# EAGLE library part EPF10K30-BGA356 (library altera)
EPF10K30 FLEX 10K family
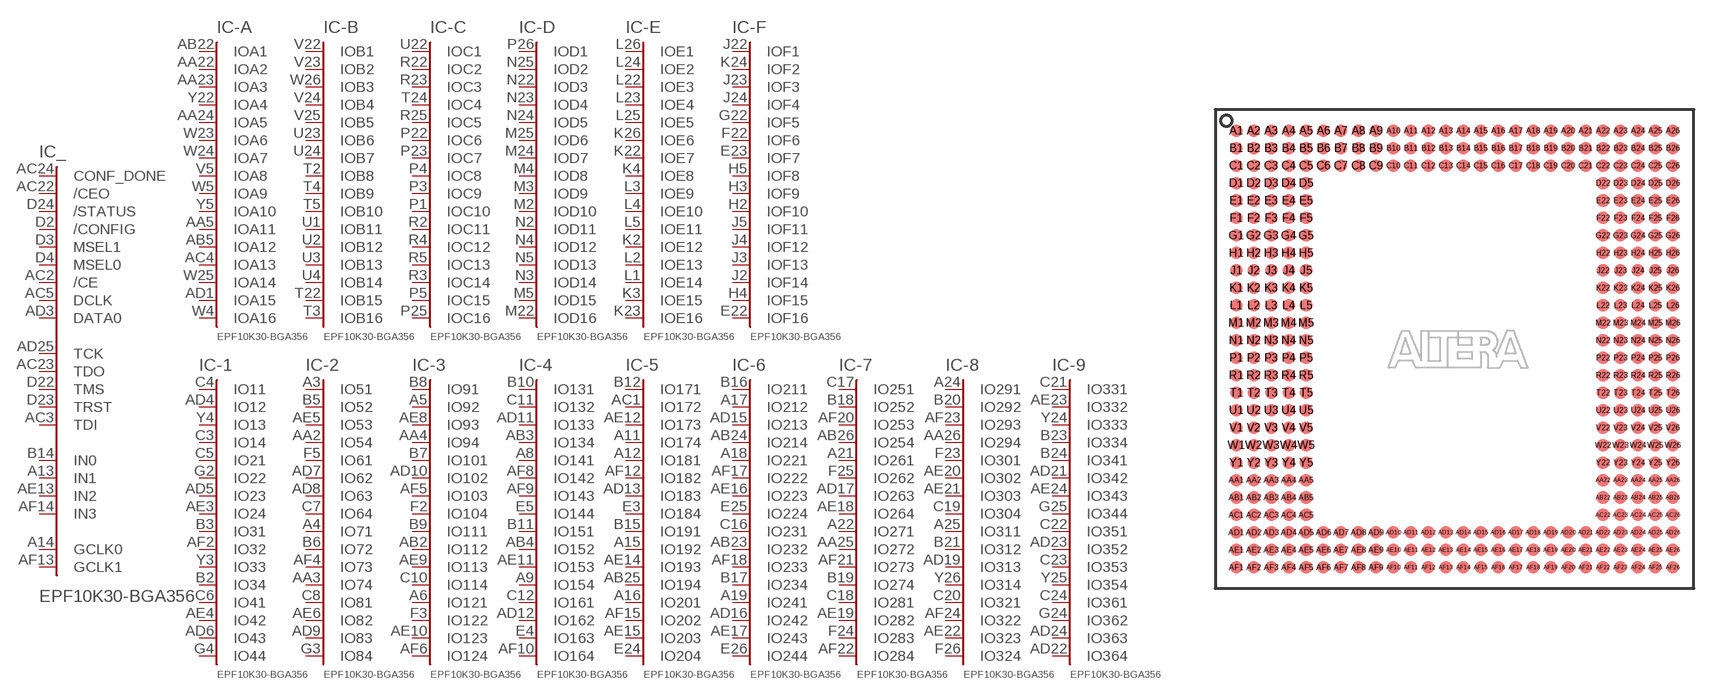
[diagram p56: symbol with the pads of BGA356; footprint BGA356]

Designator prefix IC; gates _=100R240C -A=A16 -B=B16 -C=C16 -D=D16 -E=E16 -1=IO44 -2=IO84 -3=IO124 -4=IO164 -5=IO204 -6=IO244 -7=IO284 -8=IO324 -9=IO364 -F=F16 G1=GNDINT G2=GNDINT G3=GNDINT G4=GNDINT G5=GNDINT G6=GNDINT G7=GNDINT G8=GNDINT G9=GNDINT G10=GNDINT G11=GNDINT G12=GNDINT G13=GNDINT G14=GNDINT G15=GNDINT G16=GNDINT G17=GNDINT G18=GNDINT G19=GNDINT G20=GNDINT G21=GNDINT G22=GNDINT G23=GNDINT G24=GNDINT G25=GNDINT G26=GNDINT G27=GNDINT G28=GNDINT G29=GNDINT G30=GNDINT G31=GNDINT G32=GNDINT G33=GNDINT NC1=NC NC2=NC NC3=NC NC4=NC NC5=NC NC6=NC NC7=NC NC8=NC NC9=NC NC10=NC NC11=NC NC12=NC NC13=NC NC14=NC NC15=NC NC16=NC NC17=NC NC18=NC NC19=NC NC20=NC NC21=NC NC22=NC NC23=NC NC24=NC NC25=NC NC26=NC NC27=NC NC28=NC V1=VCCINT V2=VCCINT V3=VCCINT V4=VCCINT V5=VCCINT V6=VCCINT V7=VCCINT V8=VCCINT V9=VCCINT V10=VCCINT V11=VCCINT V12=VCCINT V13=VCCINT V14=VCCINT V15=VCCINT V16=VCCINT VO1=VCCIO VO2=VCCIO VO3=VCCIO VO4=VCCIO VO5=VCCIO VO6=VCCIO VO7=VCCIO VO8=VCCIO VO9=VCCIO VO10=VCCIO VO11=VCCIO VO12=VCCIO VO13=VCCIO VO14=VCCIO VO15=VCCIO VO16=VCCIO VO17=VCCIO VO18=VCCIO VO19=VCCIO

## EPF10K30-BGA356 (MPN: EPF10K30ABC356-2; OC_FARNELL: unknown; OC_NEWARK: 51R8936)  [BGA356]
A1  V5:VCC  pwr
A2  G17:GND  pwr
A3  -2:IO51
A4  -2:IO71
A5  -3:IO92
A6  -3:IO121
A7  VO7:VCCIO  pwr
A8  -4:IO141
A9  -4:IO154
A10  G16:GND  pwr
A11  -5:IO174
A12  -5:IO181
A13  _:IN1  in
A14  _:GCLK0  in
A15  -5:IO192
A16  -5:IO201
A17  -6:IO212
A18  -6:IO221
A19  -6:IO241
A20  G15:GND  pwr
A21  -7:IO261
A22  -7:IO271
A23  VO8:VCCIO  pwr
A24  -8:IO291
A25  -8:IO311
A26  V6:VCC  pwr
AA1  V1:VCC  pwr
AA2  -2:IO54
AA3  -2:IO74
AA4  -3:IO94
AA5  -A:IOA11
AA22  -A:IOA2
AA23  -A:IOA3
AA24  -A:IOA5
AA25  -7:IO272
AA26  -8:IO294
AB1  VO1:VCCIO  pwr
AB2  -3:IO112
AB3  -4:IO134
AB4  -4:IO152
AB5  -A:IOA12
AB22  -A:IOA1
AB23  -6:IO232
AB24  -6:IO214
AB25  -5:IO194
AB26  -7:IO254
AC1  -5:IO172
AC2  _:/CE  in
AC3  _:TDI
AC4  -A:IOA13
AC5  _:DCLK  in
AC22  _:/CEO  in
AC23  _:TDO
AC24  _:CONF_DONE  in
AC25  VO2:VCCIO  pwr
AC26  NC1:NC  nc
AD1  -A:IOA15
AD2  G1:GND  pwr
AD3  _:DATA0  in
AD4  -1:IO12
AD5  -1:IO23
AD6  -1:IO43
AD7  -2:IO62
AD8  -2:IO63
AD9  -2:IO83
AD10  -3:IO102
AD11  -4:IO133
AD12  -4:IO162
AD13  -5:IO183
AD14  G2:GND  pwr
AD15  -6:IO213
AD16  -6:IO242
AD17  -7:IO263
AD18  VO3:VCCIO  pwr
AD19  -8:IO313
AD20  G3:GND  pwr
AD21  -9:IO342
AD22  -9:IO364
AD23  -9:IO352
AD24  -9:IO363
AD25  _:TCK
AD26  V2:VCC  pwr
AE1  G4:GND  pwr
AE2  G5:GND  pwr
AE3  -1:IO24
AE4  -1:IO42
AE5  -2:IO53
AE6  -2:IO82
AE7  G6:GND  pwr
AE8  -3:IO93
AE9  -3:IO113
AE10  -3:IO123
AE11  -4:IO153
AE12  -5:IO173
AE13  _:IN2  in
AE14  -5:IO193
AE15  -5:IO203
AE16  -6:IO223
AE17  -6:IO243
AE18  -7:IO264
AE19  -7:IO282
AE20  -8:IO302
AE21  -8:IO303
AE22  -8:IO323
AE23  -9:IO332
AE24  -9:IO343
AE25  G7:GND  pwr
AE26  G8:GND  pwr
AF1  V3:VCC  pwr
AF2  -1:IO32
AF3  VO4:VCCIO  pwr
AF4  -2:IO73
AF5  -3:IO103
AF6  -3:IO124
AF7  VO5:VCCIO  pwr
AF8  -4:IO142
AF9  -4:IO143
AF10  -4:IO164
AF11  G9:GND  pwr
AF12  -5:IO182
AF13  _:GCLK1  in
AF14  _:IN3  in
AF15  -5:IO202
AF16  VO6:VCCIO  pwr
AF17  -6:IO222
AF18  -6:IO233
AF19  G10:GND  pwr
AF20  -7:IO253
AF21  -7:IO273
AF22  -7:IO284
AF23  -8:IO293
AF24  -8:IO322
AF25  G18:GND  pwr
AF26  V4:VCC  pwr
B1  G14:GND  pwr
B2  -1:IO34
B3  -1:IO31
B4  VO9:VCCIO  pwr
B5  -2:IO52
B6  -2:IO72
B7  -3:IO101
B8  -3:IO91
B9  -3:IO111
B10  -4:IO131
B11  -4:IO151
B12  -5:IO171
B13  G13:GND  pwr
B14  _:IN0  in
B15  -5:IO191
B16  -6:IO211
B17  -6:IO234
B18  -7:IO252
B19  -7:IO274
B20  -8:IO292
B21  -8:IO312
B22  G12:GND  pwr
B23  -9:IO334
B24  -9:IO341
B25  G11:GND  pwr
B26  G19:GND  pwr
C1  NC2:NC  nc
C2  G20:GND  pwr
C3  -1:IO14
C4  -1:IO11
C5  -1:IO21
C6  -1:IO41
C7  -2:IO64
C8  -2:IO81
C9  G21:GND  pwr
C10  -3:IO114
C11  -4:IO132
C12  -4:IO161
C13  G22:GND  pwr
C14  V7:VCC  pwr
C15  VO10:VCCIO  pwr
C16  -6:IO231
C17  -7:IO251
C18  -7:IO281
C19  -8:IO304
C20  -8:IO321
C21  -9:IO331
C22  -9:IO351
C23  -9:IO353
C24  -9:IO361
C25  G23:GND  pwr
C26  V8:VCC  pwr
D1  NC3:NC  nc
D2  _:/CONFIG  in
D3  _:MSEL1  in
D4  _:MSEL0  in
D5  V9:VCC  pwr
D22  _:TMS
D23  _:TRST
D24  _:/STATUS  in
D25  VO11:VCCIO  pwr
D26  NC4:NC  nc
E1  NC5:NC  nc
E2  NC6:NC  nc
E3  -5:IO184
E4  -4:IO163
E5  -4:IO144
E22  -F:IOF16
E23  -F:IOF7
E24  -5:IO204
E25  -6:IO224
E26  -6:IO244
F1  V10:VCC  pwr
F2  -3:IO104
F3  -3:IO122
F4  VO12:VCCIO  pwr
F5  -2:IO61
F22  -F:IOF6
F23  -8:IO301
F24  -7:IO283
F25  -7:IO262
F26  -8:IO324
G1  NC7:NC  nc
G2  -1:IO22
G3  -2:IO84
G4  -1:IO44
G5  NC8:NC  nc
G22  -F:IOF5
G23  NC9:NC  nc
G24  -9:IO362
G25  -9:IO344
G26  NC10:NC  nc
H1  NC11:NC  nc
H2  -F:IOF10
H3  -F:IOF9
H4  -F:IOF15
H5  -F:IOF8
H22  V11:VCC  pwr
H23  G24:GND  pwr
H24  VO13:VCCIO  pwr
H25  NC12:NC  nc
H26  NC13:NC  nc
J1  V12:VCC  pwr
J2  -F:IOF14
J3  -F:IOF13
J4  -F:IOF12
J5  -F:IOF11
J22  -F:IOF1
J23  -F:IOF3
J24  -F:IOF4
J25  NC14:NC  nc
J26  G25:GND  pwr
K1  G26:GND  pwr
K2  -E:IOE12
K3  -E:IOE15
K4  -E:IOE8
K5  VO14:VCCIO  pwr
K22  -E:IOE7
K23  -E:IOE16
K24  -F:IOF2
K25  NC15:NC  nc
K26  -E:IOE6
L1  -E:IOE14
L2  -E:IOE13
L3  -E:IOE9
L4  -E:IOE10
L5  -E:IOE11
L22  -E:IOE3
L23  -E:IOE4
L24  -E:IOE2
L25  -E:IOE5
L26  -E:IOE1
M1  G27:GND  pwr
M2  -D:IOD10
M3  -D:IOD9
M4  -D:IOD8
M5  -D:IOD15
M22  -D:IOD16
M23  VO15:VCCIO  pwr
M24  -D:IOD7
M25  -D:IOD6
M26  V13:VCC  pwr
N1  V14:VCC  pwr
N2  -D:IOD11
N3  -D:IOD14
N4  -D:IOD12
N5  -D:IOD13
N22  -D:IOD3
N23  -D:IOD4
N24  -D:IOD5
N25  -D:IOD2
N26  G28:GND  pwr
P1  -C:IOC10
P2  VO16:VCCIO  pwr
P3  -C:IOC9
P4  -C:IOC8
P5  -C:IOC15
P22  -C:IOC6
P23  -C:IOC7
P24  NC16:NC  nc
P25  -C:IOC16
P26  -D:IOD1
R1  G29:GND  pwr
R2  -C:IOC11
R3  -C:IOC14
R4  -C:IOC12
R5  -C:IOC13
R22  -C:IOC2
R23  -C:IOC3
R24  NC17:NC  nc
R25  -C:IOC5
R26  G30:GND  pwr
T1  G31:GND  pwr
T2  -B:IOB8
T3  -B:IOB16
T4  -B:IOB9
T5  -B:IOB10
T22  -B:IOB15
T23  NC18:NC  nc
T24  -C:IOC4
T25  VO17:VCCIO  pwr
T26  V15:VCC  pwr
U1  -B:IOB11
U2  -B:IOB12
U3  -B:IOB13
U4  -B:IOB14
U5  V16:VCC  pwr
U22  -C:IOC1
U23  -B:IOB6
U24  -B:IOB7
U25  NC19:NC  nc
U26  G32:GND  pwr
V1  NC20:NC  nc
V2  VO18:VCCIO  pwr
V3  NC21:NC  nc
V4  NC22:NC  nc
V5  -A:IOA8
V22  -B:IOB1
V23  -B:IOB2
V24  -B:IOB4
V25  -B:IOB5
V26  NC23:NC  nc
W1  G33:GND  pwr
W2  NC24:NC  nc
W3  NC25:NC  nc
W4  -A:IOA16
W5  -A:IOA9
W22  VO19:VCCIO  pwr
W23  -A:IOA6
W24  -A:IOA7
W25  -A:IOA14
W26  -B:IOB3
Y1  NC26:NC  nc
Y2  NC27:NC  nc
Y3  -1:IO33
Y4  -1:IO13
Y5  -A:IOA10
Y22  -A:IOA4
Y23  NC28:NC  nc
Y24  -9:IO333
Y25  -9:IO354
Y26  -8:IO314

## Footprint BGA356 (pad centres in mm)
Ball Grid Array
smd 0.9 x 0.9: A1 -15.875,15.875; A2 -14.605,15.875; A3 -13.335,15.875; A4 -12.065,15.875; A5 -10.795,15.875; A6 -9.525,15.875; A7 -8.255,15.875; A8 -6.985,15.875; A9 -5.715,15.875; A10 -4.445,15.875; A11 -3.175,15.875; A12 -1.905,15.875; A13 -0.635,15.875; A14 0.635,15.875; A15 1.905,15.875; A16 3.175,15.875; A17 4.445,15.875; A18 5.715,15.875; A19 6.985,15.875; A20 8.255,15.875; A21 9.525,15.875; A22 10.795,15.875; A23 12.065,15.875; A24 13.335,15.875; A25 14.605,15.875; A26 15.875,15.875; AA1 -15.875,-9.525; AA2 -14.605,-9.525; AA3 -13.335,-9.525; AA4 -12.065,-9.525; AA5 -10.795,-9.525; AA22 10.795,-9.525; AA23 12.065,-9.525; AA24 13.335,-9.525; AA25 14.605,-9.525; AA26 15.875,-9.525; AB1 -15.875,-10.795; AB2 -14.605,-10.795; AB3 -13.335,-10.795; AB4 -12.065,-10.795; AB5 -10.795,-10.795; AB22 10.795,-10.795; AB23 12.065,-10.795; AB24 13.335,-10.795; AB25 14.605,-10.795; AB26 15.875,-10.795; AC1 -15.875,-12.065; AC2 -14.605,-12.065; AC3 -13.335,-12.065; AC4 -12.065,-12.065; AC5 -10.795,-12.065; AC22 10.795,-12.065; AC23 12.065,-12.065; AC24 13.335,-12.065; AC25 14.605,-12.065; AC26 15.875,-12.065; AD1 -15.875,-13.335; AD2 -14.605,-13.335; AD3 -13.335,-13.335; AD4 -12.065,-13.335; AD5 -10.795,-13.335; AD6 -9.525,-13.335; AD7 -8.255,-13.335; AD8 -6.985,-13.335; AD9 -5.715,-13.335; AD10 -4.445,-13.335; AD11 -3.175,-13.335; AD12 -1.905,-13.335; AD13 -0.635,-13.335; AD14 0.635,-13.335; AD15 1.905,-13.335; AD16 3.175,-13.335; AD17 4.445,-13.335; AD18 5.715,-13.335; AD19 6.985,-13.335; AD20 8.255,-13.335; AD21 9.525,-13.335; AD22 10.795,-13.335; AD23 12.065,-13.335; AD24 13.335,-13.335; AD25 14.605,-13.335; AD26 15.875,-13.335; AE1 -15.875,-14.605; AE2 -14.605,-14.605; AE3 -13.335,-14.605; AE4 -12.065,-14.605; AE5 -10.795,-14.605; AE6 -9.525,-14.605; AE7 -8.255,-14.605; AE8 -6.985,-14.605; AE9 -5.715,-14.605; AE10 -4.445,-14.605; AE11 -3.175,-14.605; AE12 -1.905,-14.605; AE13 -0.635,-14.605; AE14 0.635,-14.605; AE15 1.905,-14.605; AE16 3.175,-14.605; AE17 4.445,-14.605; AE18 5.715,-14.605; AE19 6.985,-14.605; AE20 8.255,-14.605; AE21 9.525,-14.605; AE22 10.795,-14.605; AE23 12.065,-14.605; AE24 13.335,-14.605; AE25 14.605,-14.605; AE26 15.875,-14.605; AF1 -15.875,-15.875; AF2 -14.605,-15.875; AF3 -13.335,-15.875; AF4 -12.065,-15.875; AF5 -10.795,-15.875; AF6 -9.525,-15.875; AF7 -8.255,-15.875; AF8 -6.985,-15.875; AF9 -5.715,-15.875; AF10 -4.445,-15.875; AF11 -3.175,-15.875; AF12 -1.905,-15.875; AF13 -0.635,-15.875; AF14 0.635,-15.875; AF15 1.905,-15.875; AF16 3.175,-15.875; AF17 4.445,-15.875; AF18 5.715,-15.875; AF19 6.985,-15.875; AF20 8.255,-15.875; AF21 9.525,-15.875; AF22 10.795,-15.875; AF23 12.065,-15.875; AF24 13.335,-15.875; AF25 14.605,-15.875; AF26 15.875,-15.875; B1 -15.875,14.605; B2 -14.605,14.605; B3 -13.335,14.605; B4 -12.065,14.605; B5 -10.795,14.605; B6 -9.525,14.605; B7 -8.255,14.605; B8 -6.985,14.605; B9 -5.715,14.605; B10 -4.445,14.605; B11 -3.175,14.605; B12 -1.905,14.605; B13 -0.635,14.605; B14 0.635,14.605; B15 1.905,14.605; B16 3.175,14.605; B17 4.445,14.605; B18 5.715,14.605; B19 6.985,14.605; B20 8.255,14.605; B21 9.525,14.605; B22 10.795,14.605; B23 12.065,14.605; B24 13.335,14.605; B25 14.605,14.605; B26 15.875,14.605; C1 -15.875,13.335; C2 -14.605,13.335; C3 -13.335,13.335; C4 -12.065,13.335; C5 -10.795,13.335; C6 -9.525,13.335; C7 -8.255,13.335; C8 -6.985,13.335; C9 -5.715,13.335; C10 -4.445,13.335; C11 -3.175,13.335; C12 -1.905,13.335; C13 -0.635,13.335; C14 0.635,13.335; C15 1.905,13.335; C16 3.175,13.335; C17 4.445,13.335; C18 5.715,13.335; C19 6.985,13.335; C20 8.255,13.335; C21 9.525,13.335; C22 10.795,13.335; C23 12.065,13.335; C24 13.335,13.335; C25 14.605,13.335; C26 15.875,13.335; D1 -15.875,12.065; D2 -14.605,12.065; D3 -13.335,12.065; D4 -12.065,12.065; D5 -10.795,12.065; D22 10.795,12.065; D23 12.065,12.065; D24 13.335,12.065; D25 14.605,12.065; D26 15.875,12.065; E1 -15.875,10.795; E2 -14.605,10.795; E3 -13.335,10.795; E4 -12.065,10.795; E5 -10.795,10.795; E22 10.795,10.795; E23 12.065,10.795; E24 13.335,10.795; E25 14.605,10.795; E26 15.875,10.795; F1 -15.875,9.525; F2 -14.605,9.525; F3 -13.335,9.525; F4 -12.065,9.525; F5 -10.795,9.525; F22 10.795,9.525; F23 12.065,9.525; F24 13.335,9.525; F25 14.605,9.525; F26 15.875,9.525; G1 -15.875,8.255; G2 -14.605,8.255; G3 -13.335,8.255; G4 -12.065,8.255; G5 -10.795,8.255; G22 10.795,8.255; G23 12.065,8.255; G24 13.335,8.255; G25 14.605,8.255; G26 15.875,8.255; H1 -15.875,6.985; H2 -14.605,6.985; H3 -13.335,6.985; H4 -12.065,6.985; H5 -10.795,6.985; H22 10.795,6.985; H23 12.065,6.985; H24 13.335,6.985; H25 14.605,6.985; H26 15.875,6.985; J1 -15.875,5.715; J2 -14.605,5.715; J3 -13.335,5.715; J4 -12.065,5.715; J5 -10.795,5.715; J22 10.795,5.715; J23 12.065,5.715; J24 13.335,5.715; J25 14.605,5.715; J26 15.875,5.715; K1 -15.875,4.445; K2 -14.605,4.445; K3 -13.335,4.445; K4 -12.065,4.445; K5 -10.795,4.445; K22 10.795,4.445; K23 12.065,4.445; K24 13.335,4.445; K25 14.605,4.445; K26 15.875,4.445; L1 -15.875,3.175; L2 -14.605,3.175; L3 -13.335,3.175; L4 -12.065,3.175; L5 -10.795,3.175; L22 10.795,3.175; L23 12.065,3.175; L24 13.335,3.175; L25 14.605,3.175; L26 15.875,3.175; M1 -15.875,1.905; M2 -14.605,1.905; M3 -13.335,1.905; M4 -12.065,1.905; M5 -10.795,1.905; M22 10.795,1.905; M23 12.065,1.905; M24 13.335,1.905; M25 14.605,1.905; M26 15.875,1.905; N1 -15.875,0.635; N2 -14.605,0.635; N3 -13.335,0.635; N4 -12.065,0.635; N5 -10.795,0.635; N22 10.795,0.635; N23 12.065,0.635; N24 13.335,0.635; N25 14.605,0.635; N26 15.875,0.635; P1 -15.875,-0.635; P2 -14.605,-0.635; P3 -13.335,-0.635; P4 -12.065,-0.635; P5 -10.795,-0.635; P22 10.795,-0.635; P23 12.065,-0.635; P24 13.335,-0.635; P25 14.605,-0.635; P26 15.875,-0.635; R1 -15.875,-1.905; R2 -14.605,-1.905; R3 -13.335,-1.905; R4 -12.065,-1.905; R5 -10.795,-1.905; R22 10.795,-1.905; R23 12.065,-1.905; R24 13.335,-1.905; R25 14.605,-1.905; R26 15.875,-1.905; T1 -15.875,-3.175; T2 -14.605,-3.175; T3 -13.335,-3.175; T4 -12.065,-3.175; T5 -10.795,-3.175; T22 10.795,-3.175; T23 12.065,-3.175; T24 13.335,-3.175; T25 14.605,-3.175; T26 15.875,-3.175; U1 -15.875,-4.445; U2 -14.605,-4.445; U3 -13.335,-4.445; U4 -12.065,-4.445; U5 -10.795,-4.445; U22 10.795,-4.445; U23 12.065,-4.445; U24 13.335,-4.445; U25 14.605,-4.445; U26 15.875,-4.445; V1 -15.875,-5.715; V2 -14.605,-5.715; V3 -13.335,-5.715; V4 -12.065,-5.715; V5 -10.795,-5.715; V22 10.795,-5.715; V23 12.065,-5.715; V24 13.335,-5.715; V25 14.605,-5.715; V26 15.875,-5.715; W1 -15.875,-6.985; W2 -14.605,-6.985; W3 -13.335,-6.985; W4 -12.065,-6.985; W5 -10.795,-6.985; W22 10.795,-6.985; W23 12.065,-6.985; W24 13.335,-6.985; W25 14.605,-6.985; W26 15.875,-6.985; Y1 -15.875,-8.255; Y2 -14.605,-8.255; Y3 -13.335,-8.255; Y4 -12.065,-8.255; Y5 -10.795,-8.255; Y22 10.795,-8.255; Y23 12.065,-8.255; Y24 13.335,-8.255; Y25 14.605,-8.255; Y26 15.875,-8.255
